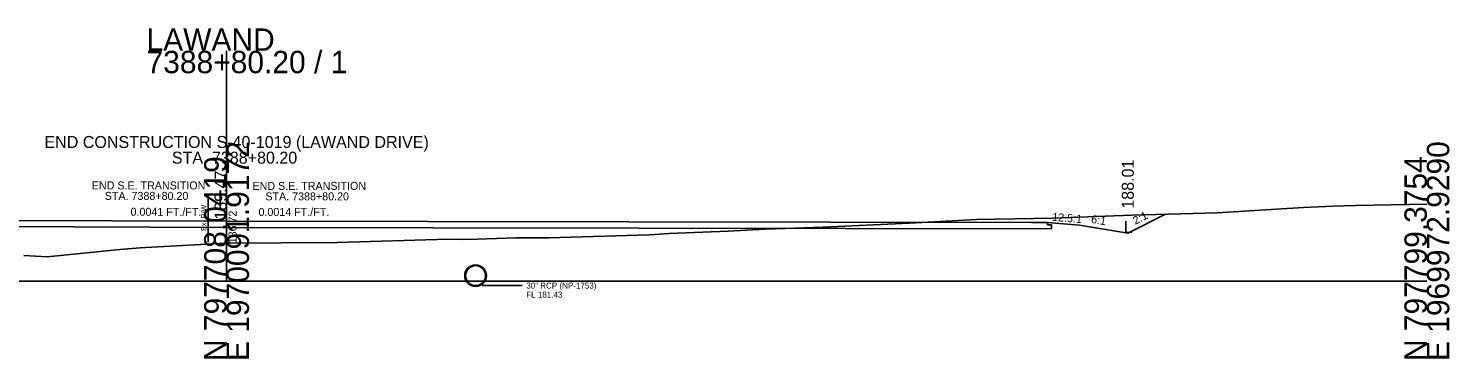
# Model space of a CAD drawing. Extents: x -26 to 303, y -10 to 1532.
# Drawn here: x 125.2 to 302.8, y 1490.3 to 1531.6 of the extents above; entities that cross this region are included whole.
import ezdxf

# ---------------------------------------------------------------- set-up
doc = ezdxf.new("R2010")
doc.units = 0
for name, color, linetype in [('RD_GPK_XS_Cell', 7, 'Continuous'), ('RD_XS_Base', 7, 'Continuous'), ('RD_XS_EarthShd', 7, 'Continuous'), ('RD_XS_ExGround', 7, 'Continuous'), ('RD_XS_ExRW', 7, 'Continuous'), ('RD_XS_Pave', 7, 'Continuous'), ('RD_XS_PaveShd', 7, 'Continuous'), ('RD_XS_Pipe', 7, 'Continuous'), ('RD_XS_TieSlope', 7, 'Continuous'), ('RD_XS_TX_Elev_EX', 7, 'Continuous'), ('RD_XS_TX_Elev_PR', 7, 'Continuous'), ('RD_XS_TX_Misc', 7, 'Continuous'), ('RD_XS_TX_MkPT', 7, 'Continuous'), ('RD_XS_TX_Notes', 7, 'Continuous'), ('RD_XS_TX_ShdSlope', 7, 'Continuous'), ('RD_XS_TX_Slope', 7, 'Continuous')]:
    doc.layers.add(name, color=color, linetype=linetype)

msp = doc.modelspace()

# ---------------------------------------------------------------- linework, layer by layer
at = {"layer": 'RD_GPK_XS_Cell'}
for p, q in [((150, 1500), (150, 1528.79)), ((0, 1500), (150, 1500)), ((150, 1500), (300, 1500))]:
    msp.add_line(p, q, dxfattribs=at)
at = {"layer": 'RD_XS_Base'}
for p, q in [((150, 1506.69), (83.74, 1506.96)), ((253.11, 1506.55), (150, 1506.69)), ((252.61, 1507.03), (252.61, 1507.33)), ((253.11, 1507.03), (252.61, 1507.03)), ((253.11, 1506.55), (253.11, 1507.03))]:
    msp.add_line(p, q, dxfattribs=at)
at = {"layer": 'RD_XS_EarthShd'}
msp.add_line((252.61, 1507.33), (256.61, 1507.01), dxfattribs=at)
at = {"layer": 'RD_XS_ExGround'}
msp.add_lwpolyline([(124.65, 1503.2), (127.58, 1503.01), (136.66, 1503.93), (139.22, 1504.15), (140.68, 1504.22), (149.88, 1504.72), (163.82, 1504.84), (177.71, 1505.22), (179.51, 1505.21), (181.31, 1505.23), (186.14, 1505.4), (190.29, 1505.42), (202.86, 1505.8), (205.32, 1505.94), (212.67, 1506.25), (215.71, 1506.42), (217.36, 1506.48), (224.56, 1506.73), (235.34, 1507.24), (243.72, 1507.69), (253.26, 1507.86), (263.13, 1508.24), (273.79, 1508.54), (284.6, 1509.19), (288.27, 1509.35), (291.08, 1509.44), (300, 1509.6)], dxfattribs=at)
at = {"layer": 'RD_XS_ExRW'}
msp.add_line((147.72, 1510.88), (147.72, 1504.88), dxfattribs=at)
at = {"layer": 'RD_XS_Pave'}
for p, q in [((150, 1507.47), (86.24, 1507.73)), ((250.61, 1507.33), (150, 1507.47))]:
    msp.add_line(p, q, dxfattribs=at)
at = {"layer": 'RD_XS_PaveShd'}
msp.add_line((250.61, 1507.33), (252.61, 1507.33), dxfattribs=at)
at = {"layer": 'RD_XS_Pipe'}
msp.add_line((181.95, 1499.43), (186.95, 1499.43), dxfattribs=at)
for radius in [1.35, 1.25]:
    msp.add_circle((181.12, 1500.68), radius, dxfattribs=at)
at = {"layer": 'RD_XS_TieSlope'}
for p, q in [((262.63, 1506.01), (267.33, 1508.36)), ((256.61, 1507.01), (262.63, 1506.01))]:
    msp.add_line(p, q, dxfattribs=at)

# ---------------------------------------------------------------- texts
at = {"layer": 'RD_GPK_XS_Cell'}
for s, p in [('LAWAND', (140, 1528.79)), ('7388+80.20 / 1', (140, 1525.99))]:
    msp.add_text(s, height=2.8, dxfattribs=at).set_placement(p)
for s, p in [('E 1970091.9172', (152.8, 1490)), ('E 1969972.9290', (302.8, 1490)), ('N 797708.0419', (150, 1490)), ('N 797799.3754', (300, 1490))]:
    msp.add_text(s, height=2.8, rotation=90, dxfattribs=at).set_placement(p)
at = {"layer": 'RD_XS_ExRW'}
msp.add_text('Ex. R/W ', height=0.65, rotation=90, dxfattribs=at).set_placement((147.47, 1506.26))
at = {"layer": 'RD_XS_Pipe'}
for s, p in [('30" RCP (NP-1753)', (187.45, 1499.06)), ('FL 181.43', (187.45, 1497.93))]:
    msp.add_text(s, height=0.75, dxfattribs=at).set_placement(p)
at = {"layer": 'RD_XS_TX_Elev_EX'}
msp.add_text('186.72', height=1, rotation=90, dxfattribs=at).set_placement((151.25, 1504.72))
at = {"layer": 'RD_XS_TX_Elev_PR'}
msp.add_text(' 189.47', height=1.5, rotation=90, dxfattribs=at).set_placement((150, 1507.13))
at = {"layer": 'RD_XS_TX_Misc'}
msp.add_text('188.01', height=1.5, rotation=90, dxfattribs=at).set_placement((263.38, 1509.05))
at = {"layer": 'RD_XS_TX_MkPT'}
msp.add_text('L', height=1.5, dxfattribs=at).set_placement((262.12, 1506.01))
at = {"layer": 'RD_XS_TX_Notes'}
for s, height, p in [('END CONSTRUCTION S-40-1019 (LAWAND DRIVE)', 1.5, (127.24, 1516.64)), ('STA. 7388+80.20', 1.5, (143.16, 1514.68)), ('END S.E. TRANSITION', 1, (133.16, 1511.46)), ('END S.E. TRANSITION', 1, (153.24, 1511.4)), ('STA. 7388+80.20', 1, (134.78, 1510.15)), ('STA. 7388+80.20', 1, (154.85, 1510.09))]:
    msp.add_text(s, height=height, dxfattribs=at).set_placement(p)
at = {"layer": 'RD_XS_TX_ShdSlope'}
msp.add_text('12.5:1', height=1, rotation=355.4261, dxfattribs=at).set_placement((253.15, 1507.54))
at = {"layer": 'RD_XS_TX_Slope'}
for s, rotation, p in [('0.0041 FT./FT.', 359.8052, (138, 1508.17)), ('0.0014 FT./FT.', 0.063, (153.99, 1508.14)), ('6:1', 350.5377, (257.99, 1507.28)), ('2:1', 26.565, (263.57, 1507.03))]:
    msp.add_text(s, height=1, rotation=rotation, dxfattribs=at).set_placement(p)

doc.saveas('drawing.dxf')
